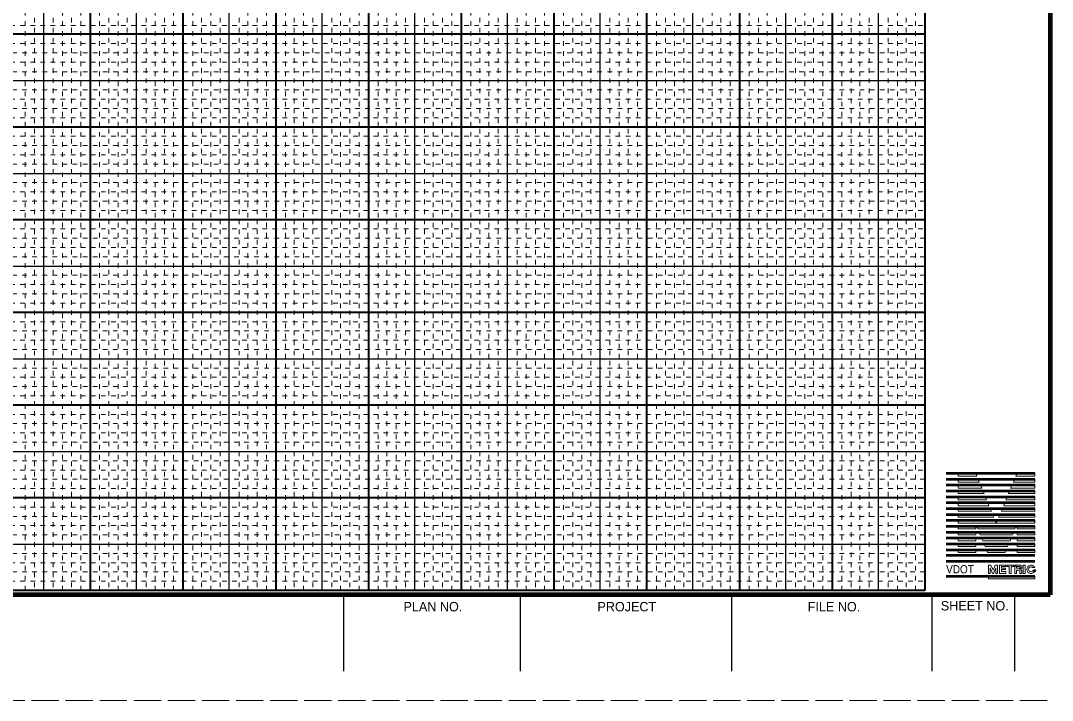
# Model space of a CAD drawing. Extents: x 224742 to 224831, y 224746 to 230645.
# Drawn here: x 224808.86 to 224831.11, y 225158.99 to 225173.66 of the extents above; entities that cross this region are included whole.
import ezdxf
from ezdxf.enums import TextEntityAlignment as Align

# ---------------------------------------------------------------- set-up
doc = ezdxf.new("R2010")
doc.units = 0
doc.header["$LTSCALE"] = 0.098
doc.header["$PDMODE"] = 32
doc.header["$PDSIZE"] = 0.049
doc.linetypes.add('DOTTED', pattern=[1.5, 0.3, -1.2])
doc.linetypes.add('LONG_DASHED', pattern=[7.5, 6, -1.5])
for name, color, linetype, lineweight in [('59', 7, 'DOTTED', 13), ('60', 7, 'Continuous', 40), ('61', 7, 'Continuous', 13), ('63', 7, 'LONG_DASHED', 13)]:
    doc.layers.add(name, color=color, linetype=linetype, lineweight=lineweight)

msp = doc.modelspace()

# ---------------------------------------------------------------- linework, layer by layer
at = {"layer": '59'}
for p, q in [((224808.9648, 225161.3649), (224808.9648, 225211.3649)), ((224809.1648, 225211.3649), (224809.1648, 225161.3649)), ((224809.5648, 225211.3649), (224809.5648, 225161.3649)), ((224809.7648, 225161.3649), (224809.7648, 225211.3649)), ((224809.9648, 225211.3649), (224809.9648, 225161.3649)), ((224810.1648, 225161.3649), (224810.1648, 225211.3649)), ((224810.5648, 225161.3649), (224810.5648, 225211.3649)), ((224810.7648, 225211.3649), (224810.7648, 225161.3649)), ((224810.9648, 225161.3649), (224810.9648, 225211.3649)), ((224811.1648, 225211.3649), (224811.1648, 225161.3649)), ((224811.5748, 225211.3649), (224811.5748, 225161.3649)), ((224811.7648, 225161.3649), (224811.7648, 225211.3649)), ((224811.9648, 225211.3649), (224811.9648, 225161.3649)), ((224812.1648, 225161.3649), (224812.1648, 225211.3649)), ((224812.5748, 225161.3649), (224812.5748, 225211.3649)), ((224812.7648, 225211.3649), (224812.7648, 225161.3649)), ((224812.9648, 225161.3649), (224812.9648, 225211.3649)), ((224813.1648, 225211.3649), (224813.1648, 225161.3649)), ((224813.5748, 225211.3649), (224813.5748, 225161.3649)), ((224813.7648, 225161.3649), (224813.7648, 225211.3649)), ((224813.9648, 225211.3649), (224813.9648, 225161.3649)), ((224814.1648, 225161.3649), (224814.1648, 225211.3649)), ((224814.5748, 225161.3649), (224814.5748, 225211.3649)), ((224814.7648, 225211.3649), (224814.7648, 225161.3649)), ((224814.9648, 225161.3649), (224814.9648, 225211.3649)), ((224815.1648, 225211.3649), (224815.1648, 225161.3649)), ((224815.5748, 225211.3649), (224815.5748, 225161.3649)), ((224815.7648, 225161.3649), (224815.7648, 225211.3649)), ((224815.9648, 225211.3649), (224815.9648, 225161.3649)), ((224816.1648, 225161.3649), (224816.1648, 225211.3649)), ((224816.5748, 225161.3649), (224816.5748, 225211.3649)), ((224816.7648, 225211.3649), (224816.7648, 225161.3649)), ((224816.9648, 225161.3649), (224816.9648, 225211.3649)), ((224817.1648, 225211.3649), (224817.1648, 225161.3649)), ((224817.5748, 225211.3649), (224817.5748, 225161.3649)), ((224817.7648, 225161.3649), (224817.7648, 225211.3649)), ((224817.9648, 225211.3649), (224817.9648, 225161.3649)), ((224818.1648, 225161.3649), (224818.1648, 225211.3649)), ((224818.5748, 225161.3649), (224818.5748, 225211.3649)), ((224818.7648, 225211.3649), (224818.7648, 225161.3649)), ((224818.9648, 225161.3649), (224818.9648, 225211.3649)), ((224819.1648, 225211.3649), (224819.1648, 225161.3649)), ((224819.5748, 225211.3649), (224819.5748, 225161.3649)), ((224819.7648, 225161.3649), (224819.7648, 225211.3649)), ((224819.9648, 225211.3649), (224819.9648, 225161.3649)), ((224820.1648, 225161.3649), (224820.1648, 225211.3649)), ((224820.5748, 225161.3649), (224820.5748, 225211.3649)), ((224820.7748, 225211.3649), (224820.7748, 225161.3649)), ((224820.9648, 225161.3649), (224820.9648, 225211.3649)), ((224821.1648, 225211.3649), (224821.1648, 225161.3649)), ((224821.5748, 225211.3649), (224821.5748, 225161.3649)), ((224821.7748, 225161.3649), (224821.7748, 225211.3649)), ((224821.9648, 225211.3649), (224821.9648, 225161.3649)), ((224822.1648, 225161.3649), (224822.1648, 225211.3649)), ((224822.5748, 225161.3649), (224822.5748, 225211.3649)), ((224822.7748, 225211.3649), (224822.7748, 225161.3649)), ((224822.9648, 225161.3649), (224822.9648, 225211.3649)), ((224823.1648, 225211.3649), (224823.1648, 225161.3649)), ((224823.5748, 225211.3649), (224823.5748, 225161.3649)), ((224823.7748, 225161.3649), (224823.7748, 225211.3649)), ((224823.9648, 225211.3649), (224823.9648, 225161.3649)), ((224824.1648, 225161.3649), (224824.1648, 225211.3649)), ((224824.5748, 225161.3649), (224824.5748, 225211.3649)), ((224824.7748, 225211.3649), (224824.7748, 225161.3649)), ((224824.9648, 225161.3649), (224824.9648, 225211.3649)), ((224825.1648, 225211.3649), (224825.1648, 225161.3649)), ((224825.5748, 225211.3649), (224825.5748, 225161.3649)), ((224825.7748, 225161.3649), (224825.7748, 225211.3649)), ((224825.9648, 225211.3649), (224825.9648, 225161.3649)), ((224826.1648, 225161.3649), (224826.1648, 225211.3649)), ((224826.5748, 225161.3649), (224826.5748, 225211.3649)), ((224826.7748, 225211.3649), (224826.7748, 225161.3649)), ((224826.9648, 225161.3649), (224826.9648, 225211.3649)), ((224827.1648, 225211.3649), (224827.1648, 225161.3649)), ((224827.5748, 225211.3649), (224827.5748, 225161.3649)), ((224827.7748, 225161.3649), (224827.7748, 225211.3649)), ((224827.9648, 225211.3649), (224827.9648, 225161.3649)), ((224828.1648, 225161.3649), (224828.1648, 225211.3649)), ((224748.3648, 225173.5549), (224828.3648, 225173.5549)), ((224748.3648, 225173.1649), (224828.3648, 225173.1649)), ((224828.3648, 225172.9649), (224748.3648, 225172.9649)), ((224748.3648, 225172.7649), (224828.3648, 225172.7649)), ((224828.3648, 225172.5549), (224748.3648, 225172.5549)), ((224828.3648, 225172.1649), (224748.3648, 225172.1649)), ((224748.3648, 225171.9649), (224828.3648, 225171.9649)), ((224828.3648, 225171.7649), (224748.3648, 225171.7649)), ((224748.3648, 225171.5649), (224828.3648, 225171.5649)), ((224748.3648, 225171.1649), (224828.3648, 225171.1649)), ((224828.3648, 225170.9649), (224748.3648, 225170.9649)), ((224748.3648, 225170.7649), (224828.3648, 225170.7649)), ((224828.3648, 225170.5649), (224748.3648, 225170.5649)), ((224828.3648, 225170.1649), (224748.3648, 225170.1649)), ((224748.3648, 225169.9649), (224828.3648, 225169.9649)), ((224828.3648, 225169.7649), (224748.3648, 225169.7649)), ((224748.3648, 225169.5649), (224828.3648, 225169.5649)), ((224748.3648, 225169.1649), (224828.3648, 225169.1649)), ((224828.3648, 225168.9649), (224748.3648, 225168.9649)), ((224748.3648, 225168.7649), (224828.3648, 225168.7649)), ((224828.3648, 225168.5649), (224748.3648, 225168.5649)), ((224828.3648, 225168.1649), (224748.3648, 225168.1649)), ((224748.3648, 225167.9649), (224828.3648, 225167.9649)), ((224828.3648, 225167.7649), (224748.3648, 225167.7649)), ((224748.3648, 225167.5649), (224828.3648, 225167.5649)), ((224748.3648, 225167.1649), (224828.3648, 225167.1649)), ((224828.3648, 225166.9649), (224748.3648, 225166.9649)), ((224748.3648, 225166.7649), (224828.3648, 225166.7649)), ((224828.3648, 225166.5649), (224748.3648, 225166.5649)), ((224828.3648, 225166.1649), (224748.3648, 225166.1649)), ((224748.3648, 225165.9649), (224828.3648, 225165.9649)), ((224828.3648, 225165.7649), (224748.3648, 225165.7649)), ((224748.3648, 225165.5649), (224828.3648, 225165.5649)), ((224748.3648, 225165.1649), (224828.3648, 225165.1649)), ((224828.3648, 225164.9649), (224748.3648, 225164.9649)), ((224748.3648, 225164.7649), (224828.3648, 225164.7649)), ((224828.3648, 225164.5649), (224748.3648, 225164.5649)), ((224828.3648, 225164.1649), (224748.3648, 225164.1649)), ((224748.3648, 225163.9649), (224828.3648, 225163.9649)), ((224828.3648, 225163.7649), (224748.3648, 225163.7649)), ((224748.3648, 225163.5649), (224828.3648, 225163.5649)), ((224748.3648, 225163.1649), (224828.3648, 225163.1649)), ((224828.3648, 225162.9649), (224748.3648, 225162.9649)), ((224748.3648, 225162.7649), (224828.3648, 225162.7649)), ((224828.3648, 225162.5649), (224748.3648, 225162.5649)), ((224828.3648, 225162.1649), (224748.3648, 225162.1649)), ((224748.3648, 225161.9649), (224828.3648, 225161.9649)), ((224828.3648, 225161.7649), (224748.3648, 225161.7649)), ((224748.3648, 225161.5649), (224828.3648, 225161.5649))]:
    msp.add_line(p, q, dxfattribs=at)
at = {"layer": '59', "linetype": 'Continuous', "lineweight": 25}
for p, q in [((224809.3648, 225161.3649), (224809.3648, 225211.3649)), ((224811.3648, 225161.3649), (224811.3648, 225211.3649)), ((224813.3648, 225161.3649), (224813.3648, 225211.3649)), ((224815.3648, 225161.3649), (224815.3648, 225211.3649)), ((224817.3648, 225161.3649), (224817.3648, 225211.3649)), ((224819.3648, 225161.3649), (224819.3648, 225211.3649)), ((224821.3648, 225161.3649), (224821.3648, 225211.3649)), ((224823.3648, 225161.3649), (224823.3648, 225211.3649)), ((224825.3648, 225161.3649), (224825.3648, 225211.3649)), ((224827.3648, 225161.3649), (224827.3648, 225211.3649)), ((224748.3648, 225172.3649), (224828.3648, 225172.3649)), ((224748.3648, 225170.3649), (224828.3648, 225170.3649)), ((224748.3648, 225168.3649), (224828.3648, 225168.3649)), ((224748.3648, 225166.3649), (224828.3648, 225166.3649)), ((224748.3648, 225164.3649), (224828.3648, 225164.3649)), ((224748.3648, 225162.3649), (224828.3648, 225162.3649))]:
    msp.add_line(p, q, dxfattribs=at)
at = {"layer": '60'}
for p, q in [((224810.3648, 225211.3649), (224810.3648, 225161.3649)), ((224812.3648, 225211.3649), (224812.3648, 225161.3649)), ((224814.3648, 225211.3649), (224814.3648, 225161.3649)), ((224816.3648, 225211.3649), (224816.3648, 225161.3649)), ((224818.3648, 225211.3649), (224818.3648, 225161.3649)), ((224820.3648, 225211.3649), (224820.3648, 225161.3649)), ((224822.3648, 225211.3649), (224822.3648, 225161.3649)), ((224824.3648, 225211.3649), (224824.3648, 225161.3649)), ((224826.3648, 225211.3649), (224826.3648, 225161.3649)), ((224828.3648, 225211.3649), (224828.3648, 225161.3649)), ((224828.3648, 225173.3649), (224748.3648, 225173.3649)), ((224828.3648, 225171.3649), (224748.3648, 225171.3649)), ((224828.3648, 225169.3649), (224748.3648, 225169.3649)), ((224828.3648, 225167.3649), (224748.3648, 225167.3649)), ((224828.3648, 225165.3649), (224748.3648, 225165.3649)), ((224828.3648, 225163.3649), (224748.3648, 225163.3649)), ((224828.3648, 225161.3649), (224748.3648, 225161.3649))]:
    msp.add_line(p, q, dxfattribs=at)
at = {"layer": '61', "lineweight": 158}
for p, q in [((224831.0648, 225215.1249), (224831.0648, 225161.2749)), ((224831.0648, 225161.2749), (224745.7148, 225161.2749))]:
    msp.add_line(p, q, dxfattribs=at)
at = {"layer": '61', "lineweight": 53}
for p, q in [((224828.8248, 225163.8949), (224830.7348, 225163.8949)), ((224828.8248, 225163.7649), (224830.7348, 225163.7649)), ((224828.8248, 225163.6449), (224830.7348, 225163.6449)), ((224828.8248, 225163.5149), (224830.7348, 225163.5149)), ((224828.8248, 225163.3849), (224830.7348, 225163.3849)), ((224828.8248, 225163.2649), (224830.7348, 225163.2649)), ((224828.8248, 225163.1349), (224830.7348, 225163.1349)), ((224828.8248, 225163.0049), (224830.7348, 225163.0049)), ((224828.8248, 225162.8849), (224830.7348, 225162.8849)), ((224828.8248, 225162.7549), (224830.7348, 225162.7549)), ((224828.8248, 225162.6249), (224830.7348, 225162.6249)), ((224828.8248, 225162.5049), (224830.7348, 225162.5049)), ((224828.8248, 225162.3749), (224830.7348, 225162.3749)), ((224828.8248, 225162.2449), (224830.7348, 225162.2449)), ((224828.8248, 225162.1249), (224830.7348, 225162.1249)), ((224828.8248, 225161.9949), (224830.7348, 225161.9949)), ((224828.8248, 225161.6749), (224830.7348, 225161.6749))]:
    msp.add_line(p, q, dxfattribs=at)
at = {"layer": '61'}
for p, q in [((224829.0848, 225163.0749), (224829.8048, 225163.0749)), ((224829.0848, 225162.9449), (224829.8548, 225162.9449)), ((224829.8848, 225162.8849), (224829.9048, 225162.8149)), ((224829.9348, 225162.8849), (224829.9048, 225162.8149)), ((224830.7348, 225162.9449), (224829.9548, 225162.9449)), ((224830.7348, 225163.0749), (224830.0148, 225163.0749)), ((224830.7348, 225161.8649), (224830.6848, 225161.8649)), ((224830.6948, 225161.7949), (224830.7348, 225161.7949))]:
    msp.add_line(p, q, dxfattribs=at)
at = {"layer": '61', "lineweight": 25}
for p, q in [((224831.0648, 225161.2749), (224815.8248, 225161.2749)), ((224815.8248, 225161.2749), (224815.8248, 225159.6249)), ((224831.0648, 225161.2749), (224815.8248, 225161.2749)), ((224819.6348, 225161.2749), (224819.6348, 225159.6249)), ((224824.2048, 225159.6249), (224824.2048, 225161.2749)), ((224828.5248, 225159.6249), (224828.5248, 225161.2749)), ((224830.3048, 225159.6249), (224830.3048, 225161.2749))]:
    msp.add_line(p, q, dxfattribs=at)
at = {"layer": '61'}
for points in [[(224829.0848, 225163.8949), (224829.0848, 225163.8349), (224829.4848, 225163.8349), (224829.4648, 225163.8949)], [(224830.7348, 225163.8949), (224830.7348, 225163.8349), (224830.3248, 225163.8349), (224830.3548, 225163.8949)], [(224829.0848, 225163.7649), (224829.0848, 225163.7049), (224829.5348, 225163.7049), (224829.5148, 225163.7649)], [(224829.0848, 225163.6449), (224829.0848, 225163.5749), (224829.5948, 225163.5749), (224829.5648, 225163.6449)], [(224830.7348, 225163.6449), (224830.7348, 225163.5749), (224830.2148, 225163.5749), (224830.2448, 225163.6449)], [(224830.7348, 225163.7649), (224830.7348, 225163.7049), (224830.2748, 225163.7049), (224830.2948, 225163.7649)], [(224829.0848, 225163.5149), (224829.0848, 225163.4549), (224829.6448, 225163.4549), (224829.6148, 225163.5149)], [(224829.0848, 225163.3849), (224829.0848, 225163.3249), (224829.6948, 225163.3249), (224829.6748, 225163.3849)], [(224830.7348, 225163.3849), (224830.7348, 225163.3249), (224830.1148, 225163.3249), (224830.1448, 225163.3849)], [(224830.7348, 225163.5149), (224830.7348, 225163.4549), (224830.1648, 225163.4549), (224830.1948, 225163.5149)], [(224829.0848, 225163.2649), (224829.0848, 225163.1949), (224829.7448, 225163.1949), (224829.7248, 225163.2649)], [(224829.0848, 225163.1349), (224829.0848, 225163.0749), (224829.8048, 225163.0749), (224829.7748, 225163.1349)], [(224830.7348, 225163.1349), (224830.7348, 225163.0749), (224830.0148, 225163.0749), (224830.0348, 225163.1349)], [(224830.7348, 225163.2649), (224830.7348, 225163.1949), (224830.0648, 225163.1949), (224830.0848, 225163.2649)], [(224829.0848, 225163.0049), (224829.0848, 225162.9449), (224829.8548, 225162.9449), (224829.8248, 225163.0049)], [(224829.0848, 225162.8849), (224829.0848, 225162.8149), (224829.9048, 225162.8149), (224829.8848, 225162.8849)], [(224830.7348, 225162.8849), (224830.7348, 225162.8149), (224829.9048, 225162.8149), (224829.9348, 225162.8849)], [(224830.7348, 225163.0049), (224830.7348, 225162.9449), (224829.9548, 225162.9449), (224829.9848, 225163.0049)], [(224829.0848, 225162.7549), (224829.0848, 225162.6949), (224829.4648, 225162.6949), (224829.4648, 225162.7549)], [(224829.4848, 225162.7549), (224829.5048, 225162.6949), (224830.3048, 225162.6949), (224830.3348, 225162.7549)], [(224830.7348, 225162.7549), (224830.7348, 225162.6949), (224830.3548, 225162.6949), (224830.3548, 225162.7549)], [(224829.0848, 225162.6249), (224829.4648, 225162.6249), (224829.4648, 225162.5649), (224829.0848, 225162.5649)], [(224829.0848, 225162.5049), (224829.4648, 225162.5049), (224829.4648, 225162.4349), (224829.0848, 225162.4349)], [(224829.5348, 225162.6249), (224829.5548, 225162.5649), (224830.2548, 225162.5649), (224830.2748, 225162.6249)], [(224829.5848, 225162.5049), (224829.6148, 225162.4349), (224830.2048, 225162.4349), (224830.2248, 225162.5049)], [(224830.7348, 225162.6249), (224830.3548, 225162.6249), (224830.3548, 225162.5649), (224830.7348, 225162.5649)], [(224830.7348, 225162.5049), (224830.3548, 225162.5049), (224830.3548, 225162.4349), (224830.7348, 225162.4349)], [(224829.0848, 225162.3749), (224829.4648, 225162.3749), (224829.4648, 225162.3149), (224829.0848, 225162.3149)], [(224829.0848, 225162.2449), (224829.4648, 225162.2449), (224829.4648, 225162.1849), (224829.0848, 225162.1849)], [(224829.6348, 225162.3749), (224829.6648, 225162.3149), (224830.1448, 225162.3149), (224830.1748, 225162.3749)], [(224829.6948, 225162.2449), (224829.7148, 225162.1849), (224830.0948, 225162.1849), (224830.1248, 225162.2449)], [(224830.7348, 225162.3749), (224830.3548, 225162.3749), (224830.3548, 225162.3149), (224830.7348, 225162.3149)], [(224830.7348, 225162.2449), (224830.3548, 225162.2449), (224830.3548, 225162.1849), (224830.7348, 225162.1849)], [(224829.7348, 225161.7349), (224829.7348, 225161.9149), (224829.7848, 225161.9149), (224829.8348, 225161.8049), (224829.8848, 225161.9149), (224829.9348, 225161.9149), (224829.9348, 225161.7349), (224829.8948, 225161.7349), (224829.8948, 225161.8549), (224829.8448, 225161.7349), (224829.8248, 225161.7349), (224829.7748, 225161.8549), (224829.7748, 225161.7349)], [(224829.9748, 225161.7349), (224829.9748, 225161.9149), (224830.1148, 225161.9149), (224830.1148, 225161.8849), (224830.0148, 225161.8849), (224830.0148, 225161.8449), (224830.1048, 225161.8449), (224830.1048, 225161.8149), (224830.0148, 225161.8149), (224830.0148, 225161.7749), (224830.1148, 225161.7749), (224830.1148, 225161.7349)], [(224830.1348, 225161.8849), (224830.1348, 225161.9149), (224830.2848, 225161.9149), (224830.2848, 225161.8849), (224830.2248, 225161.8849), (224830.2248, 225161.7349), (224830.1848, 225161.7349), (224830.1848, 225161.8849)], [(224830.3048, 225161.9149), (224830.3048, 225161.7349), (224830.3448, 225161.7349), (224830.3448, 225161.8049), (224830.3948, 225161.8049), (224830.3948, 225161.8049), (224830.4048, 225161.8049), (224830.4048, 225161.8049), (224830.4048, 225161.8049), (224830.4048, 225161.8049), (224830.4048, 225161.7949), (224830.4148, 225161.7949), (224830.4148, 225161.7849), (224830.4148, 225161.7749), (224830.4148, 225161.7549), (224830.4148, 225161.7549), (224830.4148, 225161.7449), (224830.4148, 225161.7349), (224830.4148, 225161.7349), (224830.4548, 225161.7349), (224830.4548, 225161.7449), (224830.4548, 225161.7449), (224830.4548, 225161.7449), (224830.4548, 225161.7549), (224830.4548, 225161.7849), (224830.4548, 225161.7949), (224830.4448, 225161.8049), (224830.4448, 225161.8149), (224830.4448, 225161.8149), (224830.4448, 225161.8149), (224830.4448, 225161.8149), (224830.4348, 225161.8149), (224830.4348, 225161.8249), (224830.4348, 225161.8249), (224830.4248, 225161.8249), (224830.4248, 225161.8249), (224830.4248, 225161.8249), (224830.3948, 225161.8449), (224830.3448, 225161.8449), (224830.3448, 225161.8849)], [(224830.3048, 225161.9149), (224830.3748, 225161.9149), (224830.3948, 225161.9149), (224830.3948, 225161.9149), (224830.4048, 225161.9149), (224830.4148, 225161.9149), (224830.4148, 225161.9149), (224830.4248, 225161.9149), (224830.4248, 225161.9149), (224830.4248, 225161.9149), (224830.4348, 225161.9149), (224830.4348, 225161.9049), (224830.4448, 225161.9049), (224830.4448, 225161.9049), (224830.4448, 225161.9049), (224830.4548, 225161.8949), (224830.4548, 225161.8949), (224830.4548, 225161.8949), (224830.4548, 225161.8849), (224830.4548, 225161.8849), (224830.4548, 225161.8749), (224830.4548, 225161.8649), (224830.4548, 225161.8649), (224830.4548, 225161.8549), (224830.4548, 225161.8549), (224830.4548, 225161.8549), (224830.4548, 225161.8449), (224830.4548, 225161.8449), (224830.4448, 225161.8449), (224830.4448, 225161.8449), (224830.4448, 225161.8349), (224830.4448, 225161.8349), (224830.4348, 225161.8349), (224830.4348, 225161.8349), (224830.4248, 225161.8249), (224830.4248, 225161.8249), (224830.3948, 225161.8449), (224830.3948, 225161.8449), (224830.4048, 225161.8449), (224830.4048, 225161.8449), (224830.4148, 225161.8449), (224830.4148, 225161.8549), (224830.4148, 225161.8549), (224830.4148, 225161.8549), (224830.4248, 225161.8649), (224830.4248, 225161.8649), (224830.4248, 225161.8649), (224830.4248, 225161.8749), (224830.4148, 225161.8749), (224830.4148, 225161.8749), (224830.4148, 225161.8749), (224830.4148, 225161.8849), (224830.4048, 225161.8849), (224830.4048, 225161.8849), (224830.3948, 225161.8849), (224830.3448, 225161.8849)], [(224830.4848, 225161.7349), (224830.4848, 225161.9149), (224830.5248, 225161.9149), (224830.5248, 225161.7349)], [(224829.7348, 225161.6749), (224830.7348, 225161.6749), (224830.7348, 225161.6149), (224829.7348, 225161.6149)]]:
    msp.add_lwpolyline(points, close=True, dxfattribs=at)
for radius, start, end in [(0.0894, 24.50501, 339.37361), (0.0518, 45.69947, 322.56629)]:
    msp.add_arc((224830.6538, 225161.8221), radius, start, end, dxfattribs=at)
msp.add_point((224830.7348, 225161.7949), dxfattribs=at)
at = {"layer": '63'}
msp.add_lwpolyline([(224831.1148, 225217.3949), (224742.2148, 225217.3949), (224742.2148, 225158.9949), (224831.1148, 225158.9949)], dxfattribs=at)

# ---------------------------------------------------------------- texts
at = {"layer": '61', "width": 0.9}
msp.add_text('VDOT', height=0.1778, dxfattribs=at).set_placement((224828.8248, 225161.7349))
at = {"layer": '61'}
for s, p in [('PLAN NO.', (224817.7557, 225160.9149)), ('PROJECT', (224821.9377, 225160.9149)), ('FILE NO.', (224826.405, 225160.9149)), ('SHEET NO.', (224829.4415, 225160.9341))]:
    msp.add_text(s, height=0.2032, dxfattribs=at).set_placement(p, align=Align.CENTER)

doc.saveas('drawing.dxf')
